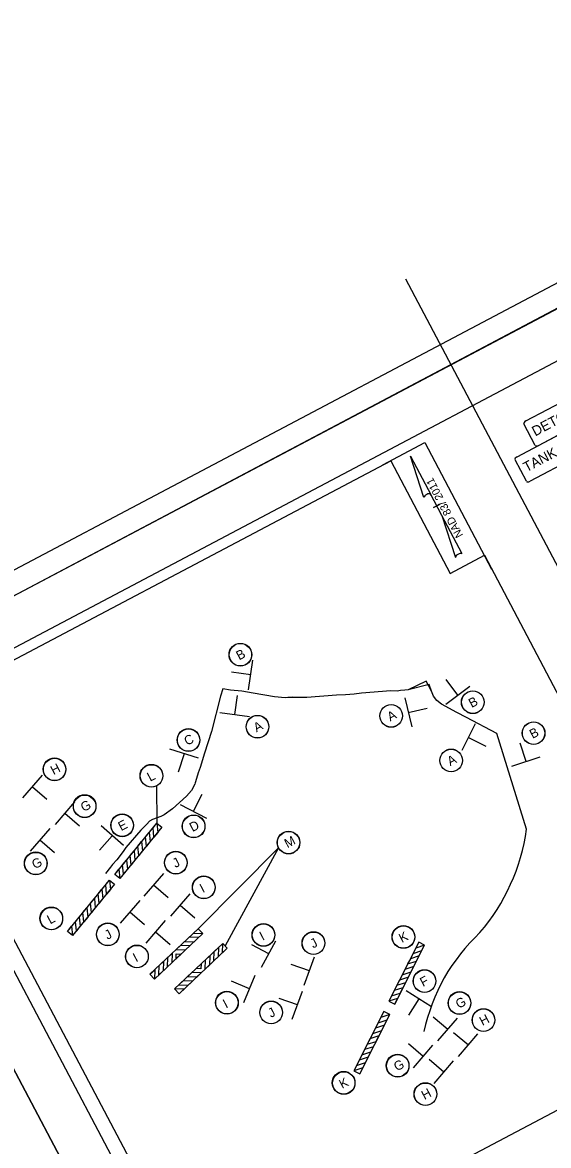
# Model space of a CAD drawing. Extents: x 1487176 to 2935813, y 497724 to 1002340.
# Drawn here: x 1488012 to 1488583, y 498480 to 499698 of the extents above; entities that cross this region are included whole.
import ezdxf

# ---------------------------------------------------------------- set-up
doc = ezdxf.new("R2010")
doc.units = 0
for name, color, linetype in [('DEV BORDER CELL', 7, 'Continuous'), ('DEV STATIONARY SIGN CELL', 7, 'Continuous'), ('DEV TYPE 3 BARRICADE CELL', 7, 'Continuous'), ('Drum Linestyle', 7, 'Continuous'), ('Exist Horizontal Alignment', 7, 'Continuous'), ('Gray Area Fill Shapes', 7, 'Continuous'), ('GS M4-8 CELL', 7, 'Continuous'), ('Prop North Arrow NAD83 for Plan Sheets CELL', 7, 'Continuous'), ('Scratch_Level_0', 7, 'Continuous'), ('Scratch_Level_1', 7, 'Continuous'), ('Scratch_Level_3', 7, 'Continuous'), ('Sheet Breakdown Map CELL', 7, 'Continuous'), ('Sheet Plot Border Outside CELL', 7, 'Continuous'), ('WZ OSDHWYEND CELL', 7, 'Continuous'), ('WZ OSDHWYL CELL', 7, 'Continuous'), ('WZ OSDHWYR CELL', 7, 'Continuous'), ('WZ OSDHWYS CELL', 7, 'Continuous'), ('WZ OSDR CELL', 7, 'Continuous')]:
    doc.layers.add(name, color=color, linetype=linetype)

msp = doc.modelspace()

# ---------------------------------------------------------------- linework, layer by layer
at = {"layer": 'DEV BORDER CELL'}
msp.add_lwpolyline([(1489116.9, 499664), (1487790.5, 498963.6), (1488280.8, 498035.1), (1489607.2, 498735.4)], close=True, dxfattribs=at)
at = {"layer": 'DEV STATIONARY SIGN CELL'}
for p, q in [((1488257.6, 498973.9), (1488262, 499006)), ((1488259.8, 498990.1), (1488239, 498992.9)), ((1488484.6, 498968.2), (1488472, 498985.1)), ((1488471.5, 498958.5), (1488497.5, 498977.8)), ((1488242.5, 498947), (1488245.4, 498967.8)), ((1488427.1, 498965.1), (1488434.6, 498933.6)), ((1488226.4, 498949.3), (1488258.5, 498944.8)), ((1488430.9, 498949.2), (1488451.3, 498954.1)), ((1488503.5, 498936.9), (1488489, 498907.9)), ((1488496.2, 498922.3), (1488515, 498912.9)), ((1488203.1, 498899.7), (1488172.2, 498909.5)), ((1488558.7, 498896.1), (1488552.2, 498916)), ((1488187.5, 498904.6), (1488181.2, 498884.6)), ((1488543.2, 498891), (1488574, 498901.1)), ((1488033.5, 498881.2), (1488012.3, 498856.7)), ((1488022.8, 498868.8), (1488038.7, 498855.1)), ((1488197.6, 498842.1), (1488207.2, 498860.8)), ((1488068.6, 498852.3), (1488047.5, 498827.8)), ((1488183.1, 498849.6), (1488211.8, 498834.8)), ((1488058, 498840), (1488073.9, 498826.3)), ((1488041.8, 498823.4), (1488020.6, 498798.8)), ((1488121.9, 498805), (1488097.4, 498826.2)), ((1488031.1, 498811), (1488047, 498797.3)), ((1488109.5, 498815.6), (1488095.8, 498799.8)), ((1488165, 498774.7), (1488143.8, 498750.2)), ((1488154.3, 498762.3), (1488170.2, 498748.6)), ((1488193.9, 498752.7), (1488172.8, 498728.2)), ((1488139.4, 498745.2), (1488118.2, 498720.7)), ((1488183.3, 498740.4), (1488199.2, 498726.7)), ((1488128.7, 498732.9), (1488144.6, 498719.2)), ((1488167.1, 498723.7), (1488145.9, 498699.2)), ((1488156.4, 498711.4), (1488172.3, 498697.7)), ((1488271.7, 498673.1), (1488287, 498701.6)), ((1488279.4, 498687.5), (1488260.9, 498697.4)), ((1488323.6, 498668.9), (1488303.8, 498676.1)), ((1488318, 498653.6), (1488329, 498684.1)), ((1488252.2, 498634.6), (1488264.7, 498664.5)), ((1488258.5, 498649.6), (1488239.1, 498657.7)), ((1488310.5, 498632.1), (1488290.8, 498639.2)), ((1488305, 498616.7), (1488316, 498647.2)), ((1488456.1, 498630.2), (1488428.6, 498647.3)), ((1488442.2, 498638.8), (1488431.2, 498621)), ((1488473.7, 498605.4), (1488457.7, 498619)), ((1488463.1, 498593), (1488484.1, 498617.6)), ((1488496.1, 498588.4), (1488480.1, 498602)), ((1488485.5, 498576), (1488506.5, 498600.7)), ((1488447, 498576.3), (1488431, 498589.9)), ((1488436.4, 498563.8), (1488457.4, 498588.5)), ((1488469.4, 498559.3), (1488453.4, 498572.9)), ((1488458.8, 498546.9), (1488479.8, 498571.5))]:
    msp.add_line(p, q, dxfattribs=at)
at = {"layer": 'DEV TYPE 3 BARRICADE CELL'}
for p, q in [((1488112.2, 498773.7), (1488157.9, 498829.4)), ((1488163.4, 498824.9), (1488117.7, 498769.2)), ((1488153.8, 498824.3), (1488157.9, 498829.4)), ((1488154.8, 498814.2), (1488153.8, 498824.3)), ((1488157.9, 498829.4), (1488158.9, 498819.2)), ((1488157.9, 498829.4), (1488163.4, 498824.9)), ((1488145.6, 498814.3), (1488149.7, 498819.3)), ((1488146.6, 498804.2), (1488145.6, 498814.3)), ((1488149.7, 498819.3), (1488150.7, 498809.2)), ((1488158.9, 498819.2), (1488154.8, 498814.2)), ((1488129, 498794.2), (1488133.2, 498799.2)), ((1488133.2, 498799.2), (1488134.2, 498789.2)), ((1488137.3, 498804.2), (1488141.4, 498809.2)), ((1488138.3, 498794.2), (1488137.3, 498804.2)), ((1488142.4, 498799.2), (1488138.3, 498794.2)), ((1488141.4, 498809.2), (1488142.4, 498799.2)), ((1488150.7, 498809.2), (1488146.6, 498804.2)), ((1488120.8, 498784.2), (1488124.9, 498789.2)), ((1488124.9, 498789.2), (1488126, 498779.2)), ((1488130.1, 498784.2), (1488129, 498794.2)), ((1488134.2, 498789.2), (1488130.1, 498784.2)), ((1488112.2, 498773.7), (1488116.7, 498779.2)), ((1488117.8, 498769.1), (1488112.2, 498773.7)), ((1488117.7, 498769.2), (1488112.2, 498773.7)), ((1488116.7, 498779.2), (1488117.8, 498769.1)), ((1488121.9, 498774.2), (1488120.8, 498784.2)), ((1488126, 498779.2), (1488121.9, 498774.2)), ((1488060.9, 498711.9), (1488106.6, 498767.6)), ((1488112, 498763.1), (1488066.4, 498707.5)), ((1488102.4, 498762.6), (1488106.6, 498767.6)), ((1488103.4, 498752.4), (1488102.4, 498762.6)), ((1488106.6, 498767.6), (1488107.6, 498757.4)), ((1488106.6, 498767.6), (1488112, 498763.1)), ((1488094.2, 498752.6), (1488098.3, 498757.6)), ((1488095.2, 498742.4), (1488094.2, 498752.6)), ((1488098.3, 498757.6), (1488099.3, 498747.4)), ((1488107.6, 498757.4), (1488103.4, 498752.4)), ((1488077.7, 498732.4), (1488081.8, 498737.5)), ((1488081.8, 498737.5), (1488082.9, 498727.4)), ((1488085.9, 498742.5), (1488090.1, 498747.5)), ((1488087, 498732.4), (1488085.9, 498742.5)), ((1488091.1, 498737.4), (1488087, 498732.4)), ((1488090.1, 498747.5), (1488091.1, 498737.4)), ((1488099.3, 498747.4), (1488095.2, 498742.4)), ((1488069.5, 498722.4), (1488073.6, 498727.4)), ((1488073.6, 498727.4), (1488074.7, 498717.4)), ((1488078.8, 498722.4), (1488077.7, 498732.4)), ((1488082.9, 498727.4), (1488078.8, 498722.4)), ((1488060.9, 498711.9), (1488065.4, 498717.4)), ((1488065.4, 498717.4), (1488066.5, 498707.4)), ((1488070.6, 498712.4), (1488069.5, 498722.4)), ((1488074.7, 498717.4), (1488070.6, 498712.4)), ((1488150.5, 498665.3), (1488202.7, 498714.8)), ((1488202.7, 498714.8), (1488197.6, 498709.9)), ((1488202.7, 498714.8), (1488207.7, 498709.6)), ((1488207.7, 498709.6), (1488202.7, 498714.8)), ((1488066.5, 498707.4), (1488060.9, 498711.9)), ((1488066.4, 498707.5), (1488060.9, 498711.9)), ((1488207.7, 498709.6), (1488155.4, 498660.1)), ((1488192.9, 498705.5), (1488188.2, 498701)), ((1488188.2, 498701), (1488198.3, 498700.7)), ((1488203, 498705.1), (1488192.9, 498705.5)), ((1488197.6, 498709.9), (1488207.7, 498709.6)), ((1488198.3, 498700.7), (1488203, 498705.1)), ((1488442.3, 498700.2), (1488409.8, 498636)), ((1488448.6, 498697), (1488442.3, 498700.2)), ((1488169.7, 498683.6), (1488174.4, 498688)), ((1488174.4, 498688), (1488174.2, 498677.9)), ((1488177.1, 498649.5), (1488229.5, 498698.7)), ((1488183.5, 498696.6), (1488178.8, 498692.1)), ((1488178.8, 498692.1), (1488188.9, 498691.8)), ((1488234.4, 498693.5), (1488182, 498644.2)), ((1488193.6, 498696.2), (1488183.5, 498696.6)), ((1488188.9, 498691.8), (1488193.6, 498696.2)), ((1488219.8, 498679.8), (1488220.1, 498689.9)), ((1488220.1, 498689.9), (1488224.8, 498694.3)), ((1488224.8, 498694.3), (1488224.6, 498684.2)), ((1488229.3, 498688.6), (1488229.5, 498698.7)), ((1488234.4, 498693.5), (1488229.3, 498688.6)), ((1488229.5, 498698.7), (1488234.4, 498693.5)), ((1488229.5, 498698.7), (1488234.4, 498693.5)), ((1488416.1, 498632.8), (1488448.6, 498697)), ((1488438.9, 498693.8), (1488436, 498688)), ((1488436, 498688), (1488445.7, 498691.2)), ((1488448.6, 498697), (1488438.9, 498693.8)), ((1488445.7, 498691.2), (1488448.6, 498697)), ((1488160.3, 498674.7), (1488165, 498679.1)), ((1488165, 498679.1), (1488164.8, 498669)), ((1488169.5, 498673.5), (1488169.7, 498683.6)), ((1488174.2, 498677.9), (1488169.5, 498673.5)), ((1488178.9, 498682.4), (1488179, 498687.5)), ((1488183.6, 498686.8), (1488178.9, 498682.4)), ((1488179, 498687.5), (1488184.2, 498687.3)), ((1488179.5, 498682.9), (1488184.2, 498687.3)), ((1488205.4, 498676.1), (1488200.7, 498671.6)), ((1488201.2, 498672.2), (1488205.9, 498676.6)), ((1488205.9, 498676.6), (1488205.8, 498671.4)), ((1488210.4, 498670.9), (1488210.6, 498681)), ((1488210.6, 498681), (1488215.4, 498685.4)), ((1488215.4, 498685.4), (1488215.1, 498675.3)), ((1488224.6, 498684.2), (1488219.8, 498679.8)), ((1488433.1, 498682.2), (1488430.1, 498676.5)), ((1488430.1, 498676.5), (1488439.8, 498679.6)), ((1488442.8, 498685.4), (1488433.1, 498682.2)), ((1488439.8, 498679.6), (1488442.8, 498685.4)), ((1488150.5, 498665.3), (1488155.6, 498670.2)), ((1488155.4, 498660.1), (1488150.5, 498665.3)), ((1488155.4, 498660.1), (1488150.5, 498665.3)), ((1488155.6, 498670.2), (1488155.4, 498660.1)), ((1488160.1, 498664.6), (1488160.3, 498674.7)), ((1488164.8, 498669), (1488160.1, 498664.6)), ((1488195.9, 498667.2), (1488191.2, 498662.8)), ((1488206, 498666.8), (1488195.9, 498667.2)), ((1488205.8, 498671.4), (1488200.7, 498671.6)), ((1488201.3, 498662.4), (1488206, 498666.8)), ((1488215.1, 498675.3), (1488210.4, 498670.9)), ((1488427.2, 498670.7), (1488424.3, 498664.9)), ((1488424.3, 498664.9), (1488433.9, 498668)), ((1488436.8, 498673.7), (1488427.2, 498670.7)), ((1488433.9, 498668), (1488436.8, 498673.7)), ((1488186.5, 498658.4), (1488181.8, 498653.9)), ((1488181.8, 498653.9), (1488191.9, 498653.5)), ((1488196.6, 498657.9), (1488186.5, 498658.4)), ((1488191.2, 498662.8), (1488201.3, 498662.4)), ((1488191.9, 498653.5), (1488196.6, 498657.9)), ((1488421.4, 498659.1), (1488418.4, 498653.4)), ((1488418.4, 498653.4), (1488428.1, 498656.4)), ((1488431, 498662.2), (1488421.4, 498659.1)), ((1488428.1, 498656.4), (1488431, 498662.2)), ((1488182, 498644.2), (1488177.1, 498649.5)), ((1488177.1, 498649.5), (1488182, 498644.2)), ((1488187.2, 498649.1), (1488177.1, 498649.5)), ((1488182, 498644.2), (1488187.2, 498649.1)), ((1488419.3, 498639.1), (1488409.6, 498636)), ((1488415.5, 498647.6), (1488412.6, 498641.8)), ((1488412.6, 498641.8), (1488422.2, 498644.9)), ((1488425.1, 498650.6), (1488415.5, 498647.6)), ((1488416.1, 498632.8), (1488419.3, 498639.1)), ((1488422.2, 498644.9), (1488425.1, 498650.6)), ((1488409.6, 498636), (1488416.1, 498632.8)), ((1488409.8, 498636), (1488416.1, 498632.8)), ((1488404.4, 498624.8), (1488371.9, 498560.6)), ((1488378.2, 498557.4), (1488410.7, 498621.6)), ((1488401.1, 498618.4), (1488398.1, 498612.7)), ((1488398.1, 498612.7), (1488407.8, 498615.8)), ((1488410.7, 498621.6), (1488401.1, 498618.4)), ((1488410.7, 498621.6), (1488404.4, 498624.8)), ((1488407.8, 498615.8), (1488410.7, 498621.6)), ((1488395.2, 498606.9), (1488392.3, 498601.1)), ((1488392.3, 498601.1), (1488402, 498604.3)), ((1488404.9, 498610.1), (1488395.2, 498606.9)), ((1488402, 498604.3), (1488404.9, 498610.1)), ((1488389.3, 498595.3), (1488386.4, 498589.6)), ((1488386.4, 498589.6), (1488396, 498592.6)), ((1488399, 498598.4), (1488389.3, 498595.3)), ((1488396, 498592.6), (1488399, 498598.4)), ((1488383.5, 498583.8), (1488380.6, 498578)), ((1488380.6, 498578), (1488390.2, 498581.1)), ((1488393.1, 498586.8), (1488383.5, 498583.8)), ((1488390.2, 498581.1), (1488393.1, 498586.8)), ((1488377.6, 498572.2), (1488374.7, 498566.5)), ((1488374.7, 498566.5), (1488384.3, 498569.5)), ((1488387.3, 498575.3), (1488377.6, 498572.2)), ((1488384.3, 498569.5), (1488387.3, 498575.3)), ((1488381.4, 498563.7), (1488371.8, 498560.7)), ((1488371.8, 498560.7), (1488378.2, 498557.4)), ((1488371.9, 498560.6), (1488378.2, 498557.4)), ((1488378.2, 498557.4), (1488381.4, 498563.7))]:
    msp.add_line(p, q, dxfattribs=at)
at = {"layer": 'Drum Linestyle'}
for p, q in [((1488559.3, 498822.6), (1488526.8, 498926.6)), ((1488107.7, 498781.5), (1488102.3, 498774.7)), ((1488109.8, 498784.3), (1488107.7, 498781.5))]:
    msp.add_line(p, q, dxfattribs=at)
for points in [[(1488450.2, 498983.1), (1488430.6, 498973.9), (1488427.2, 498973.4), (1488422.5, 498973.1), (1488418.9, 498972.6), (1488412, 498972.7), (1488380, 498970.4)], [(1488526.8, 498926.6), (1488494, 498943.9), (1488483.4, 498949.2), (1488466.8, 498958.5), (1488461.8, 498962.4), (1488458.3, 498967.1), (1488456, 498972.4), (1488450.2, 498983.1)], [(1488229.4, 498975.1), (1488227, 498967.1), (1488217.4, 498928.8), (1488209.8, 498905.2), (1488205, 498889.8)], [(1488300.2, 498965.5), (1488297.4, 498965.3), (1488285.7, 498966.2), (1488262.4, 498970.3), (1488250.1, 498972.4), (1488237.9, 498973.6), (1488229.4, 498975.1)], [(1488380, 498970.4), (1488372, 498969.2), (1488362.7, 498968.3), (1488353.1, 498968), (1488320.9, 498965.7), (1488311.6, 498965.6), (1488300.2, 498965.5)], [(1488205, 498889.8), (1488202.9, 498884), (1488200.9, 498877.6), (1488199.6, 498873), (1488199.2, 498871.5)], [(1488199.2, 498871.5), (1488195.4, 498864.8), (1488190.2, 498858.5), (1488174.9, 498844.7), (1488166, 498838.3)], [(1488166, 498838.3), (1488162.4, 498836.5), (1488153.4, 498833.3), (1488150, 498831.4), (1488146.9, 498828.3)], [(1488146.9, 498828.3), (1488140.4, 498821.8), (1488124.3, 498803), (1488121.3, 498798.5), (1488114.6, 498789.6), (1488109.8, 498784.3)]]:
    msp.add_lwpolyline(points, dxfattribs=at)
for centre, radius, start, end in [((1488340.1, 498854.2), 221.5, 319.5474, 351.8139), ((1488648.9, 498560.2), 205.6, 133.0273, 167.9481)]:
    msp.add_arc(centre, radius, start, end, dxfattribs=at)
at = {"layer": 'Exist Horizontal Alignment'}
for p, q in [((1488559.3, 498822.6), (1488526.8, 498926.6)), ((1488107.7, 498781.5), (1488102.3, 498774.7)), ((1488109.8, 498784.3), (1488107.7, 498781.5))]:
    msp.add_line(p, q, dxfattribs=at)
for points in [[(1488229.4, 498975.1), (1488227, 498967.1), (1488217.4, 498928.8), (1488209.8, 498905.2), (1488205, 498889.8)], [(1488305.2, 498965.9), (1488297.4, 498965.3), (1488285.7, 498966.2), (1488262.4, 498970.3), (1488250.1, 498972.4), (1488237.9, 498973.6), (1488229.4, 498975.1)], [(1488380, 498970.4), (1488372, 498969.2), (1488362.7, 498968.3), (1488353.1, 498968), (1488320.9, 498965.7), (1488311.6, 498965.6), (1488305.2, 498965.9)], [(1488453.6, 498979.8), (1488430.6, 498973.9), (1488427.2, 498973.4), (1488422.5, 498973.1), (1488418.9, 498972.6), (1488412, 498972.7), (1488380, 498970.4)], [(1488526.8, 498926.6), (1488494, 498943.9), (1488483.4, 498949.2), (1488466.8, 498958.5), (1488461.8, 498962.4), (1488458.3, 498967.1), (1488456, 498972.4), (1488453.6, 498979.8)], [(1488205, 498889.8), (1488202.9, 498884), (1488200.9, 498877.6), (1488199.6, 498873), (1488199.2, 498871.5)], [(1488199.2, 498871.5), (1488195.4, 498864.8), (1488190.2, 498858.5), (1488174.9, 498844.7), (1488166, 498838.3)], [(1488166, 498838.3), (1488162.4, 498836.5), (1488153.4, 498833.3), (1488150, 498831.4), (1488146.9, 498828.3)], [(1488146.9, 498828.3), (1488140.4, 498821.8), (1488124.3, 498803), (1488121.3, 498798.5), (1488114.6, 498789.6), (1488109.8, 498784.3)]]:
    msp.add_lwpolyline(points, dxfattribs=at)
for centre, radius, start, end in [((1488340.1, 498854.2), 221.5, 319.5474, 351.8139), ((1488648.9, 498560.2), 205.6, 133.0273, 167.9481)]:
    msp.add_arc(centre, radius, start, end, dxfattribs=at)
at = {"layer": 'Gray Area Fill Shapes'}
for centre in [(1488248.6, 499012), (1488500.9, 498960.5), (1488412.3, 498945.6), (1488267.2, 498933.9), (1488192.4, 498919.3), (1488566.9, 498926.9), (1488477.4, 498897.3), (1488047, 498887.5), (1488152.1, 498880.5), (1488079.6, 498847.5), (1488120.4, 498826.8), (1488197.9, 498825.8), (1488301, 498808.1), (1488026.5, 498785.4), (1488178.6, 498786.3), (1488208.9, 498759.5), (1488043.5, 498725.7), (1488104.8, 498708.5), (1488273.7, 498707.9), (1488425.6, 498705.7), (1488328, 498699), (1488136.4, 498684.5), (1488448.6, 498657.8), (1488234.1, 498634.4), (1488486.6, 498634), (1488282.1, 498623.8), (1488512.6, 498615.5), (1488419.4, 498566.1), (1488360.8, 498547.4), (1488449.5, 498535.2)]:
    msp.add_circle(centre, 12.2, dxfattribs=at)
at = {"layer": 'GS M4-8 CELL'}
msp.add_line((1488609.9, 499224.9), (1488563, 499200.1), dxfattribs=at)
for points in [[(1488549, 499226.7), (1488595.9, 499251.4)], [(1488559.1, 499200.1), (1488546.8, 499223.5)]]:
    msp.add_lwpolyline(points, dxfattribs=at)
for centre, start_param, end_param in [((1488549.8, 499225.1), 4.712162, 6.283185), ((1488562.2, 499201.7), 0, 1.570796)]:
    msp.add_ellipse(centre, major_axis=(-3.1, -1.63), ratio=0.5, start_param=start_param, end_param=end_param, dxfattribs=at)
at = {"layer": 'Prop North Arrow NAD83 for Plan Sheets CELL'}
for p, q in [((1488433.4, 499227.3), (1488433.4, 499227.3)), ((1488433.4, 499227.3), (1488433.4, 499227.3)), ((1488447.8, 499182.5), (1488433.4, 499227.3)), ((1488433.4, 499227.3), (1488455.7, 499185)), ((1488467.3, 499163.1), (1488455.1, 499186.3)), ((1488455.7, 499185), (1488455.1, 499186.2)), ((1488458.4, 499171.5), (1488465.5, 499175.2)), ((1488458.4, 499171.5), (1488458.3, 499171.5)), ((1488461.5, 499173.1), (1488458.4, 499171.5)), ((1488467.3, 499163.1), (1488482, 499117.4)), ((1488489.3, 499121.5), (1488467.3, 499163.1))]:
    msp.add_line(p, q, dxfattribs=at)
for centre, start_param, end_param in [((1488451.7, 499184), 0.216388, 2.908219), ((1488485.8, 499119.2), 0.201328, 3.141593)]:
    msp.add_ellipse(centre, major_axis=(3.76, 1.95), ratio=0.461098, start_param=start_param, end_param=end_param, dxfattribs=at)
at = {"layer": 'Scratch_Level_0'}
msp.add_lwpolyline([(1489096.1, 499596.4), (1487858.1, 498942.7), (1488301.6, 498102.6), (1489078.8, 498513), (1489023.6, 498617.6), (1489484.4, 498860.9)], close=True, dxfattribs=at)
at = {"layer": 'Scratch_Level_1'}
msp.add_line((1488427.9, 499419.8), (1488968, 498396.9), dxfattribs=at)
at = {"layer": 'Scratch_Level_3'}
msp.add_lwpolyline([(1487790.5, 498963.6), (1488958.9, 499581.5), (1489116.9, 499664), (1489607.2, 498735.4), (1488280.8, 498035.1)], close=True, dxfattribs=at)
at = {"layer": 'Sheet Breakdown Map CELL'}
msp.add_lwpolyline([(1487877.3, 498940.2), (1488411.8, 499222.4), (1488476.4, 499100.2), (1488513.4, 499119.8), (1488779.2, 498616.3), (1488207.7, 498314.6)], close=True, dxfattribs=at)
msp.add_lwpolyline([(1487877.3, 498940.2), (1488411.8, 499222.4), (1488476.4, 499100.2), (1488513.4, 499119.8), (1488779.2, 498616.3), (1488207.7, 498314.6)], close=True, dxfattribs=at)
at = {"layer": 'Sheet Plot Border Outside CELL'}
msp.add_lwpolyline([(1488148.3, 497936.8), (1489641, 498725), (1489127.4, 499697.7), (1487634.7, 498909.6)], close=True, dxfattribs=at)
at = {"layer": 'WZ OSDHWYEND CELL'}
for centre in [(1488046.8, 498887.7), (1488079.6, 498847.8), (1488026.5, 498785.7)]:
    msp.add_circle(centre, 12.3, dxfattribs=at)
at = {"layer": 'WZ OSDHWYL CELL'}
for p, q in [((1488157.7, 498869.9), (1488157.9, 498829.4)), ((1488290.1, 498802.4), (1488202.7, 498714.8)), ((1488290.1, 498802.4), (1488232, 498696.1))]:
    msp.add_line(p, q, dxfattribs=at)
for centre in [(1488248.6, 499012), (1488500.8, 498960.4), (1488566.9, 498926.9), (1488197.9, 498825.8)]:
    msp.add_circle(centre, 12.3, dxfattribs=at)
at = {"layer": 'WZ OSDHWYR CELL'}
for points in [[(1488558.5, 499265.6), (1488605.3, 499290.3)], [(1488568.6, 499239), (1488556.2, 499262.4)], [(1488619.3, 499263.8), (1488572.5, 499239)]]:
    msp.add_lwpolyline(points, dxfattribs=at)
for centre in [(1488412.3, 498945.6), (1488267.2, 498933.9), (1488477.4, 498897.3)]:
    msp.add_circle(centre, 12.3, dxfattribs=at)
for centre, start_param, end_param in [((1488559.3, 499264), 4.712162, 6.283185), ((1488571.7, 499240.6), 0, 1.570796)]:
    msp.add_ellipse(centre, major_axis=(-3.1, -1.63), ratio=0.5, start_param=start_param, end_param=end_param, dxfattribs=at)
at = {"layer": 'WZ OSDHWYS CELL'}
for centre in [(1488192.3, 498919.5), (1488152, 498880.7), (1488120.3, 498827.1), (1488300.9, 498808.3), (1488178.5, 498786.5), (1488208.8, 498759.7), (1488043.4, 498726), (1488104.7, 498708.7), (1488273.6, 498708.1), (1488425.5, 498705.9), (1488327.9, 498699.2), (1488136.3, 498684.7), (1488448.5, 498658), (1488233.9, 498634.6), (1488486.5, 498634.2), (1488282, 498624), (1488512.5, 498615.7), (1488419.3, 498566.3), (1488360.7, 498547.7), (1488449.4, 498535.4)]:
    msp.add_circle(centre, 12.3, dxfattribs=at)
at = {"layer": 'WZ OSDR CELL'}
for p, q in [((1488411.8, 499222.4), (1488476.4, 499100.2)), ((1488476.4, 499100.2), (1488513.4, 499119.8))]:
    msp.add_line(p, q, dxfattribs=at)
msp.add_lwpolyline([(1488403.2, 499217.9), (1488448.9, 499242), (1488521.3, 499104.7)], dxfattribs=at)

# ---------------------------------------------------------------- texts
at = {"layer": 'GS M4-8 CELL'}
msp.add_text('TANK TOWN RD', height=10.83, rotation=27.8354, dxfattribs=at).set_placement((1488559.2, 499209.7))
at = {"layer": 'Prop North Arrow NAD83 for Plan Sheets CELL'}
msp.add_text('NAD 83/ 2011', height=8.5, rotation=117.8111, dxfattribs=at).set_placement((1488490.6, 499141.5))
at = {"layer": 'WZ OSDHWYR CELL'}
msp.add_text('DETOUR', height=10.83, rotation=27.8351, dxfattribs=at).set_placement((1488568.6, 499248.6))
at = {"layer": 'WZ OSDHWYS CELL'}
for s, p in [('C', (1488190.8, 498913.1)), ('F', (1488446.8, 498651.5))]:
    msp.add_text(s, height=10, rotation=27.8351, dxfattribs=at).set_placement(p)
at = {"layer": 'WZ OSDR CELL'}
for s, p in [('B', (1488247.3, 499005.7)), ('B', (1488499.6, 498954.1)), ('A', (1488411.2, 498939.4)), ('A', (1488266.1, 498927.6)), ('B', (1488565.7, 498920.6)), ('A', (1488476.3, 498891.1)), ('H', (1488045.8, 498881.3)), ('L', (1488150.7, 498874.1)), ('G', (1488078.5, 498841.3)), ('E', (1488119.2, 498820.5)), ('D', (1488196.6, 498819.5)), ('M', (1488299.6, 498802)), ('G', (1488025.5, 498779.2)), ('J', (1488178.2, 498780.5)), ('I', (1488207.8, 498753.3)), ('L', (1488042.1, 498719.4)), ('J', (1488104.4, 498702.6)), ('I', (1488272.6, 498701.6)), ('J', (1488327.6, 498693.2)), ('K', (1488423.9, 498699.2)), ('I', (1488135.3, 498678.2)), ('G', (1488485.5, 498627.8)), ('I', (1488232.9, 498628.2)), ('J', (1488281.8, 498617.9)), ('H', (1488511.4, 498609.2)), ('G', (1488418.4, 498559.9)), ('K', (1488359.1, 498540.9)), ('H', (1488448.4, 498528.9))]:
    msp.add_text(s, height=10, rotation=27.8351, dxfattribs=at).set_placement(p)

doc.saveas('drawing.dxf')
